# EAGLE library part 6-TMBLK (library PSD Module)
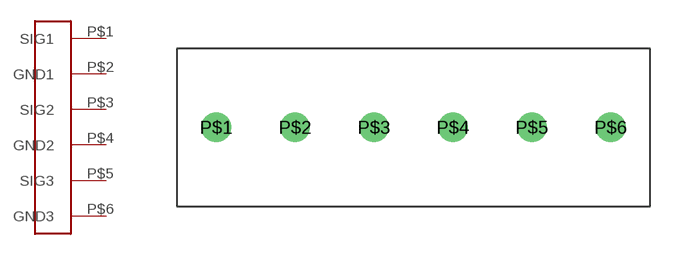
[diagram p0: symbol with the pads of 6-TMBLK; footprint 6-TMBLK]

Designator prefix -

## 6-TMBLK  [6-TMBLK]
P$1  SIG1
P$2  GND1
P$3  SIG2
P$4  GND2
P$5  SIG3
P$6  GND3

## Footprint 6-TMBLK (pad centres in mm)
drill 1.27 round: P$1 -12.7,0; P$2 -7.62,0; P$3 -2.54,0; P$4 2.54,0; P$5 7.62,0; P$6 12.7,0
